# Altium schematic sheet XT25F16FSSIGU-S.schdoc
size 127 x 101 mm
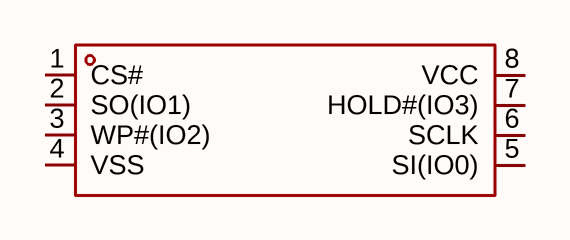
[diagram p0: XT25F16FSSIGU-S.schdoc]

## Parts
U?  xt25f16fssigu-s  [SOIC-8_L5.3-W5.3-P1.27-LS8.0-BL]  (value not drawn)

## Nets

Not connected (* = marked no-connect by the designer): U? 1(CS#) 2(SO(IO1)) 3(WP#(IO2)) 4(VSS) 5(SI(IO0)) 6(SCLK) 7(HOLD#(IO3)) 8(VCC)

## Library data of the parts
U? = xt25f16fssigu-s: 接口类型:SPI;存储容量:16Mbit;时钟频率(fc):133MHz;; Manufacturer: XTX(芯天下); AddInBom: yes; ModelId: f83d990ad74f400caf5ac920b7771508; ModelName: SOIC-8_L5.3-W5.3-H1.9-LS7.9-P1.27; ModelTransform: 208.661,311.25654,0,0,0,0,-0.0005,0.0005,0; Interface: SPI; Memory Size: 16Mbit; Clock Frequency: 133MHz; Voltage - Supply: 2.3V~3.6V; Standby Supply Current: 0.3uA; Program / Erase Cycles: 100000次; Page Programming Time (Tpp): 400us; Block Erase Time(tBE): 150ms@(32KB); Data Retention - TDR (Year): 20年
